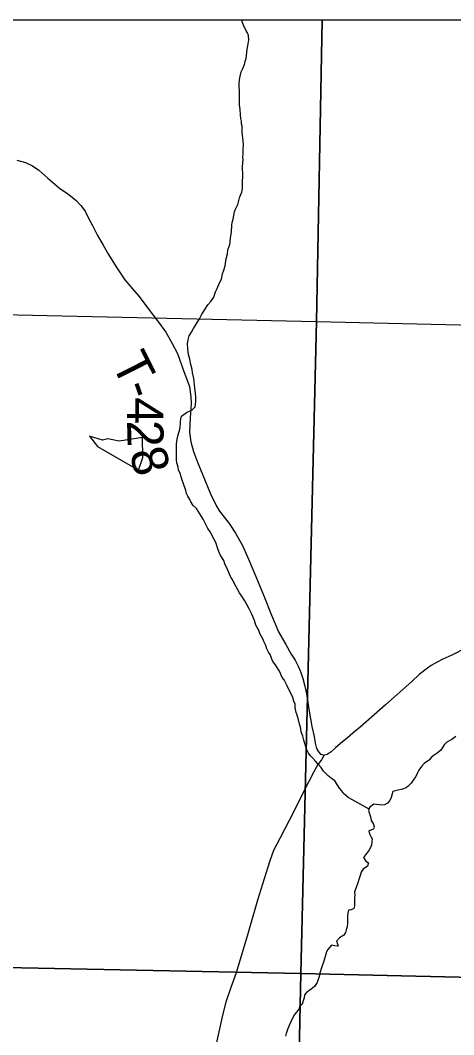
# Model space of a CAD drawing. Extents: x 0 to 34, y 0 to 22.
# Drawn here: x 5.636 to 6.316, y 19.309 to 20.9 of the extents above; entities that cross this region are included whole.
import ezdxf

# ---------------------------------------------------------------- set-up
doc = ezdxf.new("R2010")
doc.units = 0
for name, color, linetype in [('GM_X_Corporation', 7, 'Continuous'), ('GM_X_County_Road', 7, 'Continuous'), ('GM_X_Minor_Lake', 7, 'Continuous'), ('GM_X_Minor_River', 7, 'Continuous'), ('GM_X_Township_Road', 7, 'Continuous'), ('GM_X_Township_Road_Text', 7, 'Continuous')]:
    doc.layers.add(name, color=color, linetype=linetype)

msp = doc.modelspace()

# ---------------------------------------------------------------- linework, layer by layer
at = {"layer": 'GM_X_Corporation'}
for points in [[(4.9914, 16.3477), (5.6931, 16.3352), (5.9938, 16.3204), (6.9309, 16.303), (7.0302, 16.2995), (7.0491, 16.2993), (8.0233, 16.275), (8.785, 16.2515), (8.9, 16.2485), (8.9, 20.9), (2.1, 20.9)], [(4.9914, 16.3477), (5.6931, 16.3352), (5.9938, 16.3204), (6.9309, 16.303), (7.0302, 16.2995), (7.0306, 16.367), (7.0337, 16.3927), (7.0334, 16.423), (7.0339, 16.4517), (7.0342, 16.5147), (7.0361, 16.5712), (7.0442, 17.0463), (7.0729, 18.3402), (7.0876, 19.4092), (7.1008, 19.81), (7.1249, 20.7061), (7.1302, 20.9), (2.2795, 20.9)]]:
    msp.add_lwpolyline(points, dxfattribs=at)
for points in [[(6.1094, 20.9), (5.08, 20.9), (5.0677, 20.4508), (6.1008, 20.4274)], [(7.1255, 20.9), (6.1094, 20.9), (6.1008, 20.4274), (7.1142, 20.404), (7.1198, 20.6337)], [(6.1008, 20.4274), (6.0762, 19.405), (5.0447, 19.4257), (5.0677, 20.4508)], [(6.1008, 20.4274), (7.1142, 20.404), (7.1126, 20.3262), (7.1064, 20.0249), (7.1003, 19.7246), (7.0936, 19.421), (7.0925, 19.3811), (6.0762, 19.405)], [(5.0447, 19.4257), (6.0762, 19.405), (6.0547, 18.3798), (5.0167, 18.3983)], [(6.0762, 19.405), (7.0925, 19.3811), (7.0882, 19.1112), (7.0832, 18.8066), (7.0725, 18.3472), (6.0547, 18.3798)]]:
    msp.add_lwpolyline(points, close=True, dxfattribs=at)
at = {"layer": 'GM_X_County_Road'}
msp.add_lwpolyline([(6.3355, 19.9157), (6.3131, 19.9044), (6.2988, 19.8978), (6.2891, 19.8928), (6.2807, 19.8878), (6.275, 19.884), (6.2619, 19.874), (6.2501, 19.8631), (6.2089, 19.8262), (6.1694, 19.7913), (6.1576, 19.782), (6.1493, 19.7745), (6.1386, 19.7657), (6.1304, 19.7587), (6.1236, 19.7528), (6.1175, 19.7485), (6.1125, 19.7473), (6.1087, 19.7398), (6.103, 19.7328), (6.0967, 19.7213), (6.082, 19.6932), (6.0652, 19.6587), (6.0437, 19.6175), (6.0332, 19.5978), (6.0273, 19.5814), (6.0185, 19.5536), (6.0083, 19.5198), (5.9931, 19.467), (5.9745, 19.4058), (5.9661, 19.3827), (5.9586, 19.3601), (5.9539, 19.3417), (5.9389, 19.2759)], dxfattribs=at)
at = {"layer": 'GM_X_Minor_Lake'}
for points in [[(5.8277, 20.2454), (5.7909, 20.24), (5.7731, 20.2437), (5.7651, 20.2414), (5.7443, 20.2475), (5.7568, 20.2316), (5.8214, 20.1945)], [(5.8214, 20.1945), (5.8281, 20.2142), (5.8277, 20.2454)]]:
    msp.add_lwpolyline(points, dxfattribs=at)
at = {"layer": 'GM_X_Minor_River'}
for points in [[(5.9104, 20.3191), (5.9097, 20.3237), (5.9081, 20.3381), (5.9062, 20.3472), (5.9058, 20.3525), (5.9035, 20.3601), (5.902, 20.3684), (5.8997, 20.376), (5.8989, 20.3848), (5.8985, 20.3931), (5.8992, 20.3988), (5.9007, 20.4049), (5.9045, 20.411), (5.9079, 20.4166), (5.9128, 20.425), (5.9169, 20.4318), (5.9203, 20.4379), (5.9252, 20.4463), (5.9301, 20.4539), (5.935, 20.4588), (5.9396, 20.4657), (5.9422, 20.474), (5.9448, 20.4793), (5.9486, 20.4884), (5.9516, 20.4941), (5.9531, 20.5025), (5.9546, 20.5063), (5.9572, 20.5146), (5.9591, 20.526), (5.961, 20.5336), (5.9617, 20.5397), (5.9647, 20.5484), (5.9658, 20.5583), (5.9673, 20.5678), (5.968, 20.5788), (5.9684, 20.5826), (5.9699, 20.5879), (5.9718, 20.5997), (5.9737, 20.6039), (5.977, 20.6111), (5.9797, 20.6217), (5.9812, 20.6259), (5.9834, 20.6304), (5.9846, 20.6354), (5.9845, 20.6456), (5.9849, 20.6566), (5.9848, 20.6699), (5.9852, 20.6767), (5.9856, 20.6817), (5.9852, 20.6855), (5.9855, 20.6904), (5.9855, 20.698), (5.9859, 20.7041), (5.9855, 20.7113), (5.9851, 20.7151), (5.9847, 20.7196), (5.9843, 20.7245), (5.9839, 20.7299), (5.9839, 20.734), (5.9831, 20.7378), (5.9831, 20.7416), (5.982, 20.7462), (5.9816, 20.7515), (5.9808, 20.7602), (5.98, 20.7674), (5.9799, 20.7894), (5.9795, 20.7959), (5.9795, 20.8019), (5.9803, 20.8099), (5.9825, 20.8194), (5.9851, 20.8243), (5.9878, 20.8308), (5.9889, 20.8357), (5.9904, 20.8403), (5.9908, 20.8448), (5.9919, 20.8547), (5.993, 20.86), (5.9945, 20.8691), (5.9941, 20.8763), (5.9926, 20.8801), (5.9899, 20.8843), (5.9861, 20.8923), (5.9842, 20.8976), (5.9838, 20.9)], [(6.1832, 19.6628), (6.1559, 19.678), (6.1503, 19.681), (6.1461, 19.6844), (6.1423, 19.6879), (6.1404, 19.6916), (6.1366, 19.6958), (6.1293, 19.7072), (6.124, 19.7106), (6.1191, 19.7151), (6.1119, 19.7223), (6.1081, 19.728), (6.1027, 19.7337), (6.0989, 19.7378), (6.0948, 19.7424), (6.0906, 19.7466), (6.0879, 19.7507), (6.0856, 19.7557), (6.0841, 19.7606), (6.0806, 19.7708), (6.0795, 19.7769), (6.0768, 19.7841), (6.0757, 19.7913), (6.0738, 19.7958), (6.0722, 19.8027), (6.0703, 19.8099), (6.0688, 19.8144), (6.0672, 19.822), (6.0672, 19.8273), (6.0653, 19.8319), (6.0638, 19.8379), (6.0607, 19.8436), (6.0573, 19.8501), (6.0539, 19.8569), (6.0497, 19.8656), (6.047, 19.8694), (6.0424, 19.8793), (6.036, 19.8895), (6.0314, 19.8955), (6.0295, 19.9012), (6.028, 19.905), (6.0253, 19.9088), (6.023, 19.9141), (6.0211, 19.9194), (6.0188, 19.9244), (6.0165, 19.9297), (6.0123, 19.9369), (6.0097, 19.9441), (6.0055, 19.9513), (6.0036, 19.9585), (5.999, 19.9687), (5.9952, 19.9771), (5.9914, 19.9839), (5.9883, 19.9892), (5.983, 19.9975), (5.9799, 20.0017), (5.9746, 20.0112), (5.9681, 20.0233), (5.9658, 20.0275), (5.9616, 20.0373), (5.9571, 20.0472), (5.9552, 20.0529), (5.9495, 20.0616), (5.9464, 20.0695), (5.9426, 20.0809), (5.9399, 20.0855), (5.9338, 20.0976), (5.93, 20.1029), (5.9228, 20.1177), (5.9125, 20.134), (5.9072, 20.1389), (5.9034, 20.1446), (5.9018, 20.1484), (5.8988, 20.1537), (5.8969, 20.1578), (5.8957, 20.1624), (5.8915, 20.1745), (5.89, 20.1787), (5.8866, 20.1889), (5.8839, 20.195), (5.8835, 20.1988), (5.8816, 20.206), (5.8812, 20.2098), (5.8808, 20.2162), (5.8808, 20.2246), (5.8811, 20.2356), (5.8822, 20.2428), (5.8837, 20.2496), (5.886, 20.2584), (5.8867, 20.2626), (5.8875, 20.2671), (5.8875, 20.2709), (5.8878, 20.2751), (5.8886, 20.2792), (5.8965, 20.285), (5.9056, 20.2888), (5.9101, 20.2937), (5.9109, 20.2975), (5.9112, 20.3024), (5.9112, 20.3093), (5.9104, 20.3191)], [(6.3194, 19.7766), (6.3129, 19.7717), (6.3054, 19.7675), (6.3012, 19.7633), (6.2956, 19.7553), (6.2899, 19.7504), (6.2853, 19.7473), (6.2808, 19.7439), (6.2778, 19.7401), (6.2698, 19.734), (6.2653, 19.7298), (6.2615, 19.7238), (6.2585, 19.7184), (6.2566, 19.7139), (6.2536, 19.7097), (6.2491, 19.7032), (6.2453, 19.6991), (6.2412, 19.696), (6.2355, 19.6941), (6.2268, 19.6918), (6.2207, 19.6903), (6.2196, 19.6865), (6.2177, 19.6808), (6.2158, 19.6762), (6.212, 19.6721), (6.2075, 19.6694), (6.2033, 19.669), (6.1996, 19.6694), (6.195, 19.6701), (6.1908, 19.6705), (6.184, 19.6652), (6.1825, 19.6606), (6.1837, 19.6553), (6.1852, 19.6508), (6.1867, 19.6447), (6.1894, 19.6401), (6.1913, 19.6356), (6.1902, 19.631), (6.1826, 19.6284), (6.1841, 19.6238), (6.1861, 19.6196), (6.188, 19.6159), (6.1876, 19.6109), (6.1869, 19.6064), (6.1838, 19.5995), (6.1808, 19.5954), (6.1774, 19.5912), (6.1744, 19.5866), (6.1782, 19.5813), (6.1824, 19.5783), (6.1805, 19.573), (6.1741, 19.5684), (6.1707, 19.5638), (6.1696, 19.5601), (6.1669, 19.5521), (6.1658, 19.5471), (6.1628, 19.5396), (6.1602, 19.5327), (6.1606, 19.5282)], [(6.1606, 19.5282), (6.1602, 19.5232), (6.1602, 19.5111), (6.1591, 19.5069), (6.1549, 19.5046), (6.1508, 19.5042), (6.15, 19.4993), (6.1493, 19.4948), (6.1493, 19.4841), (6.1486, 19.4781), (6.1475, 19.4731), (6.1463, 19.469), (6.1437, 19.4648), (6.1369, 19.4606), (6.1323, 19.4557), (6.1339, 19.4515), (6.1346, 19.4477), (6.1293, 19.4481), (6.124, 19.4492), (6.1187, 19.4423), (6.1165, 19.4386), (6.1142, 19.4317), (6.112, 19.4241), (6.1086, 19.4139), (6.106, 19.4055), (6.1049, 19.4002), (6.1033, 19.3957), (6.1015, 19.3907), (6.0973, 19.3846), (6.0924, 19.3801), (6.0848, 19.3751), (6.0818, 19.3713), (6.0815, 19.3668), (6.0796, 19.3622), (6.0781, 19.3569), (6.0739, 19.3531), (6.0732, 19.3489), (6.0694, 19.3444), (6.0664, 19.3406), (6.0619, 19.3326), (6.0577, 19.3231), (6.0551, 19.317), (6.0532, 19.3106), (6.0521, 19.3068)]]:
    msp.add_lwpolyline(points, dxfattribs=at)
at = {"layer": 'GM_X_Township_Road'}
msp.add_lwpolyline([(5.6306, 20.6804), (5.644, 20.6768), (5.6548, 20.6718), (5.6648, 20.6651), (5.679, 20.6526), (5.6976, 20.6368), (5.712, 20.6265), (5.7235, 20.6174), (5.7309, 20.6095), (5.7378, 20.6005), (5.7426, 20.5909), (5.7495, 20.5773), (5.7567, 20.5636), (5.7659, 20.5473), (5.7741, 20.5328), (5.7863, 20.5132), (5.8, 20.4929), (5.8121, 20.4788), (5.8225, 20.4666), (5.8358, 20.4484), (5.8513, 20.4288), (5.864, 20.4108), (5.8742, 20.393), (5.8828, 20.3771), (5.8926, 20.3489), (5.9012, 20.3254), (5.9034, 20.3094), (5.9038, 20.2982), (5.9022, 20.2765), (5.9016, 20.254), (5.9034, 20.2387), (5.9075, 20.2236), (5.914, 20.207), (5.9222, 20.1866), (5.9345, 20.1572), (5.9439, 20.138), (5.9484, 20.1298), (5.9635, 20.1106), (5.9735, 20.0957), (5.9845, 20.076), (5.9923, 20.0585), (6.0029, 20.0339), (6.0181, 19.997), (6.0303, 19.9671), (6.0412, 19.941), (6.0526, 19.9207), (6.061, 19.906), (6.0673, 19.8962), (6.072, 19.8868), (6.0755, 19.8788), (6.0792, 19.8674), (6.0826, 19.8555), (6.0851, 19.8436), (6.0892, 19.8162), (6.0935, 19.7922), (6.0969, 19.7768), (6.0987, 19.7659), (6.1008, 19.758), (6.1039, 19.7525), (6.1069, 19.7489), (6.1125, 19.7473)], dxfattribs=at)

# ---------------------------------------------------------------- texts
at = {"layer": 'GM_X_Township_Road_Text'}
for s, rotation, p in [('T', 296.8046, (5.7781, 20.3621)), ('-', 289.4916, (5.7965, 20.3259)), ('4', 269.8126, (5.8034, 20.3089)), ('2', 271.4372, (5.8033, 20.2722)), ('8', 285.6613, (5.8065, 20.222))]:
    msp.add_text(s, height=0.0568, rotation=rotation, dxfattribs=at).set_placement(p)

doc.saveas('drawing.dxf')
